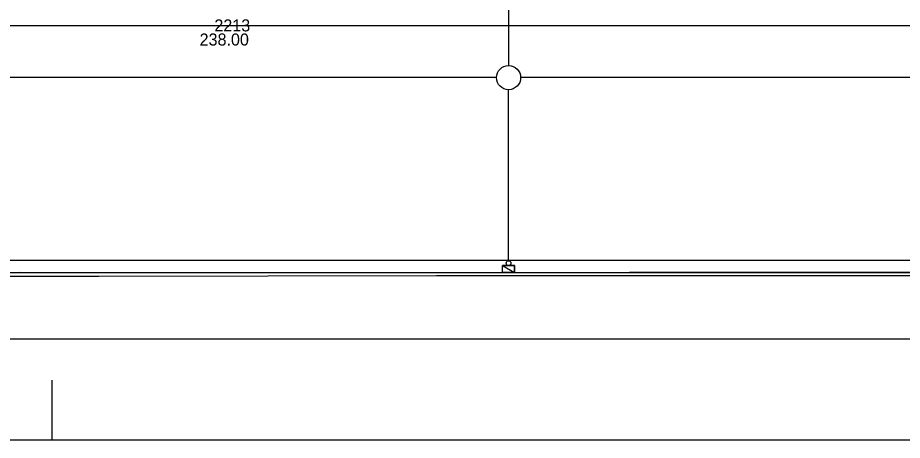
# Model space of a CAD drawing. Extents: x -264165 to -263733, y -1242319 to -1242245.
# Drawn here: x -263924.28 to -263887.58, y -1242319.19 to -1242301.66 of the extents above; entities that cross this region are included whole.
import ezdxf

# ---------------------------------------------------------------- set-up
doc = ezdxf.new("R2010")
doc.units = 0
for name, color, linetype in [('KFA_BOD_CISLO', 7, 'Continuous'), ('KFA_BOD_VYSKA', 7, 'Continuous'), ('PROJEKT_OBRUBNIKY_KOMUNIKACIE', 7, 'Continuous'), ('PROJEKT_TDZ_VODOROVNE', 7, 'Continuous'), ('RAM_NA_TLAC_1-250', 7, 'Continuous'), ('SITUACIA_DSP_2D', 7, 'Continuous'), ('SO_20-1_OBRUBNIKY_DOLNA_HRANA', 7, 'Continuous'), ('SO_20-1_OBRUBNIKY_HORNA_HRANA', 7, 'Continuous')]:
    doc.layers.add(name, color=color, linetype=linetype)

msp = doc.modelspace()

# ---------------------------------------------------------------- linework, layer by layer
at = {"layer": 'PROJEKT_OBRUBNIKY_KOMUNIKACIE'}
for p, q in [((-263980.94, -1242312.232), (-263924.192, -1242312.232)), ((-263842.601, -1242312.24), (-263924.192, -1242312.232)), ((-264038.443, -1242314.982), (-263836.403, -1242314.982))]:
    msp.add_line(p, q, dxfattribs=at)
at = {"layer": 'PROJEKT_TDZ_VODOROVNE'}
for p, q in [((-263932.58, -1242301.982), (-263913.841, -1242301.982)), ((-263913.857, -1242301.982), (-263816.374, -1242301.982)), ((-263842.661, -1242311.732), (-263980.94, -1242311.732))]:
    msp.add_line(p, q, dxfattribs=at)
at = {"layer": 'RAM_NA_TLAC_1-250'}
msp.add_line((-263922.863, -1242316.685), (-263922.863, -1242319.185), dxfattribs=at)
msp.add_lwpolyline([(-264165.363, -1242244.935), (-263732.863, -1242244.935), (-263732.863, -1242319.185), (-264165.363, -1242319.185)], close=True, dxfattribs=at)
at = {"layer": 'SITUACIA_DSP_2D'}
for p, q in [((-263903.913, -1242299.147), (-263903.913, -1242303.647)), ((-263904.413, -1242304.147), (-263953.413, -1242304.147)), ((-263854.415, -1242304.147), (-263903.413, -1242304.147)), ((-263903.913, -1242311.742), (-263903.913, -1242304.647)), ((-263904.163, -1242311.942), (-263903.663, -1242311.942)), ((-263904.163, -1242312.232), (-263904.163, -1242311.942)), ((-263904.163, -1242311.942), (-263903.663, -1242312.232)), ((-263904.163, -1242311.942), (-263903.663, -1242312.232)), ((-263903.663, -1242311.942), (-263904.163, -1242311.942)), ((-263903.663, -1242311.942), (-263903.663, -1242312.232)), ((-263903.663, -1242312.232), (-263903.663, -1242311.942)), ((-263980.94, -1242312.232), (-263857.327, -1242312.232)), ((-263842.601, -1242312.24), (-263924.192, -1242312.232)), ((-263903.663, -1242312.232), (-263904.163, -1242312.232)), ((-264038.443, -1242314.982), (-263836.403, -1242314.982))]:
    msp.add_line(p, q, dxfattribs=at)
for centre, radius in [((-263903.913, -1242304.147), 0.5), ((-263903.913, -1242311.842), 0.1)]:
    msp.add_circle(centre, radius, dxfattribs=at)
at = {"layer": 'SO_20-1_OBRUBNIKY_DOLNA_HRANA'}
msp.add_lwpolyline([(-263927.909, -1242312.235), (-263920.91, -1242312.234), (-263913.915, -1242312.225), (-263906.912, -1242312.227), (-263898.896, -1242312.208), (-263891.9, -1242312.209), (-263883.905, -1242312.21), (-263878.731, -1242312.212), (-263870.923, -1242312.226), (-263863.907, -1242312.232), (-263855.93, -1242312.232)], dxfattribs=at)
at = {"layer": 'SO_20-1_OBRUBNIKY_HORNA_HRANA'}
msp.add_lwpolyline([(-263927.907, -1242312.381), (-263920.909, -1242312.378), (-263913.91, -1242312.365), (-263906.907, -1242312.358), (-263898.91, -1242312.357), (-263891.902, -1242312.354), (-263883.907, -1242312.356), (-263878.731, -1242312.358), (-263870.924, -1242312.368), (-263863.913, -1242312.368), (-263855.926, -1242312.378)], dxfattribs=at)

# ---------------------------------------------------------------- texts
at = {"layer": 'KFA_BOD_CISLO'}
msp.add_text('2213', height=0.5, dxfattribs=at).set_placement((-263916.122, -1242302.231))
at = {"layer": 'KFA_BOD_VYSKA'}
msp.add_text('238.00', height=0.5, dxfattribs=at).set_placement((-263916.734, -1242302.816))

doc.saveas('drawing.dxf')
